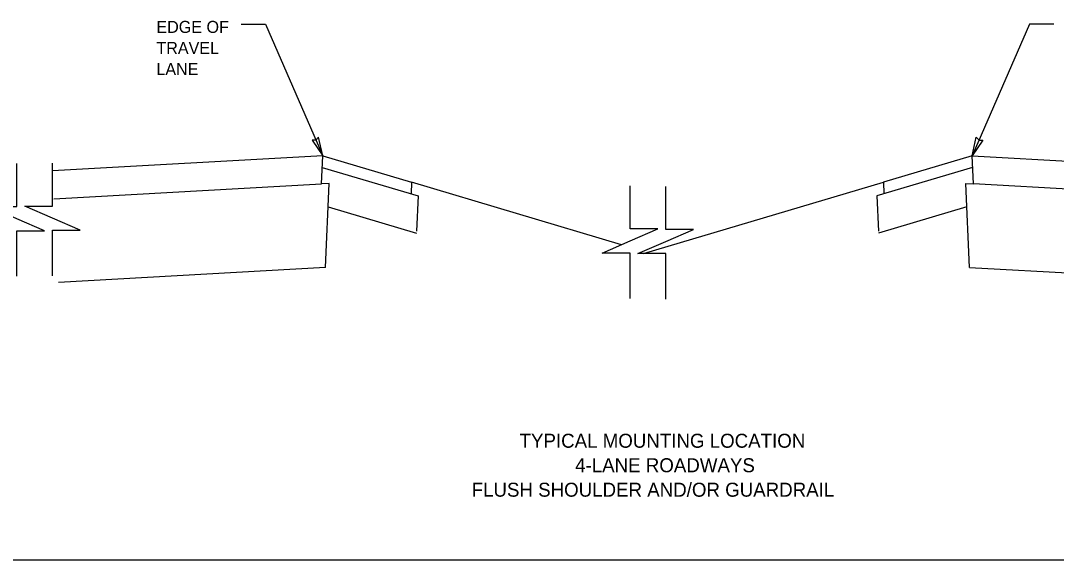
# Model space of a CAD drawing. Extents: x 56768 to 57406, y 11696 to 12105.
# Drawn here: x 56946.4 to 57187.3, y 11934.3 to 12059.7 of the extents above; entities that cross this region are included whole.
import ezdxf

# ---------------------------------------------------------------- set-up
doc = ezdxf.new("R2010")
doc.units = 0
for name, color, linetype in [('Default', 7, 'Continuous'), ('DimLines_dp', 7, 'Continuous'), ('SheetBorder_dp', 7, 'Continuous'), ('TextTables', 7, 'Continuous'), ('XSGrdLine_ex', 7, 'Continuous')]:
    doc.layers.add(name, color=color, linetype=linetype)

msp = doc.modelspace()

# ---------------------------------------------------------------- linework, layer by layer
at = {"layer": 'Default'}
for points in [[(56945.5, 12000.28), (56945.5, 12010.84), (56951.96, 12010.84), (56945.5, 12013.65), (56939.04, 12016.47), (56945.5, 12016.47), (56945.5, 12026.47)], [(56953.8, 12000.41), (56953.8, 12010.97), (56960.26, 12010.97), (56953.8, 12013.79), (56947.34, 12016.6), (56953.8, 12016.6), (56953.8, 12026.6)], [(57088.14, 11995.11), (57088.14, 12005.67), (57081.68, 12005.67), (57088.14, 12008.48), (57094.6, 12011.3), (57088.14, 12011.3), (57088.14, 12021.3)], [(57096.44, 11994.98), (57096.44, 12005.54), (57089.98, 12005.54), (57096.44, 12008.35), (57102.9, 12011.17), (57096.44, 12011.17), (57096.44, 12021.17)]]:
    msp.add_lwpolyline(points, dxfattribs=at)
at = {"layer": 'DimLines_dp'}
for p, q in [((56997.71, 12058.87), (57003.36, 12058.87)), ((57003.36, 12058.87), (57016.68, 12028.26)), ((57181.04, 12058.87), (57167.72, 12028.26)), ((57186.68, 12058.87), (57181.04, 12058.87)), ((57015.08, 12031.95), (57014.2, 12031.92)), ((57014.2, 12031.92), (57016.68, 12028.26)), ((57015.71, 12032.58), (57015.08, 12031.95)), ((57016.68, 12028.26), (57015.71, 12032.58)), ((57167.72, 12028.26), (57168.68, 12032.58)), ((57170.19, 12031.92), (57167.72, 12028.26)), ((57168.68, 12032.58), (57169.32, 12031.95)), ((57169.32, 12031.95), (57170.19, 12031.92))]:
    msp.add_line(p, q, dxfattribs=at)
at = {"layer": 'SheetBorder_dp'}
msp.add_line((57405.89, 11934.25), (56789.89, 11934.25), dxfattribs=at)
at = {"layer": 'XSGrdLine_ex'}
for p, q in [((57016.68, 12028.26), (56953.8, 12024.78)), ((57016.39, 12021.75), (57016.68, 12028.26)), ((57016.68, 12028.26), (57037.32, 12022.13)), ((57167.72, 12028.26), (57147.08, 12022.13)), ((57168, 12021.75), (57167.72, 12028.26)), ((57167.72, 12028.26), (57230.6, 12024.78)), ((57016.56, 12025.59), (57038.85, 12018.97)), ((57167.83, 12025.59), (57145.55, 12018.97)), ((56954.16, 12018.3), (57016.39, 12021.75)), ((57018.14, 12021.85), (57016.39, 12021.75)), ((57017.27, 12002.3), (57018.14, 12021.85)), ((57037.32, 12022.13), (57037.2, 12019.46)), ((57086.14, 12007.61), (57037.32, 12022.13)), ((57091.28, 12005.54), (57147.08, 12022.13)), ((57147.08, 12022.13), (57147.2, 12019.46)), ((57166.26, 12021.85), (57168, 12021.75)), ((57167.12, 12002.3), (57166.26, 12021.85)), ((57230.24, 12018.3), (57168, 12021.75)), ((57038.85, 12018.97), (57038.49, 12010.74)), ((57145.55, 12018.97), (57145.91, 12010.74)), ((57017.9, 12016.44), (57038.47, 12010.32)), ((57166.5, 12016.44), (57145.93, 12010.32)), ((57017.27, 12002.3), (56955.23, 11998.86)), ((57167.12, 12002.3), (57229.16, 11998.86))]:
    msp.add_line(p, q, dxfattribs=at)

# ---------------------------------------------------------------- texts
at = {"layer": 'DimLines_dp'}
for s, p in [('EDGE OF ', (56977.98, 12056.84)), ('TRAVEL ', (56977.98, 12051.94)), ('LANE', (56977.98, 12047.04))]:
    msp.add_text(s, height=2.8, dxfattribs=at).set_placement(p)
at = {"layer": 'TextTables'}
for s, p in [('TYPICAL MOUNTING LOCATION', (57062.45, 11960.41)), ('4-LANE ROADWAYS', (57075.37, 11954.72)), ('FLUSH SHOULDER AND/OR GUARDRAIL', (57051.3, 11949.03))]:
    msp.add_text(s, height=3.2524, dxfattribs=at).set_placement(p)

doc.saveas('drawing.dxf')
